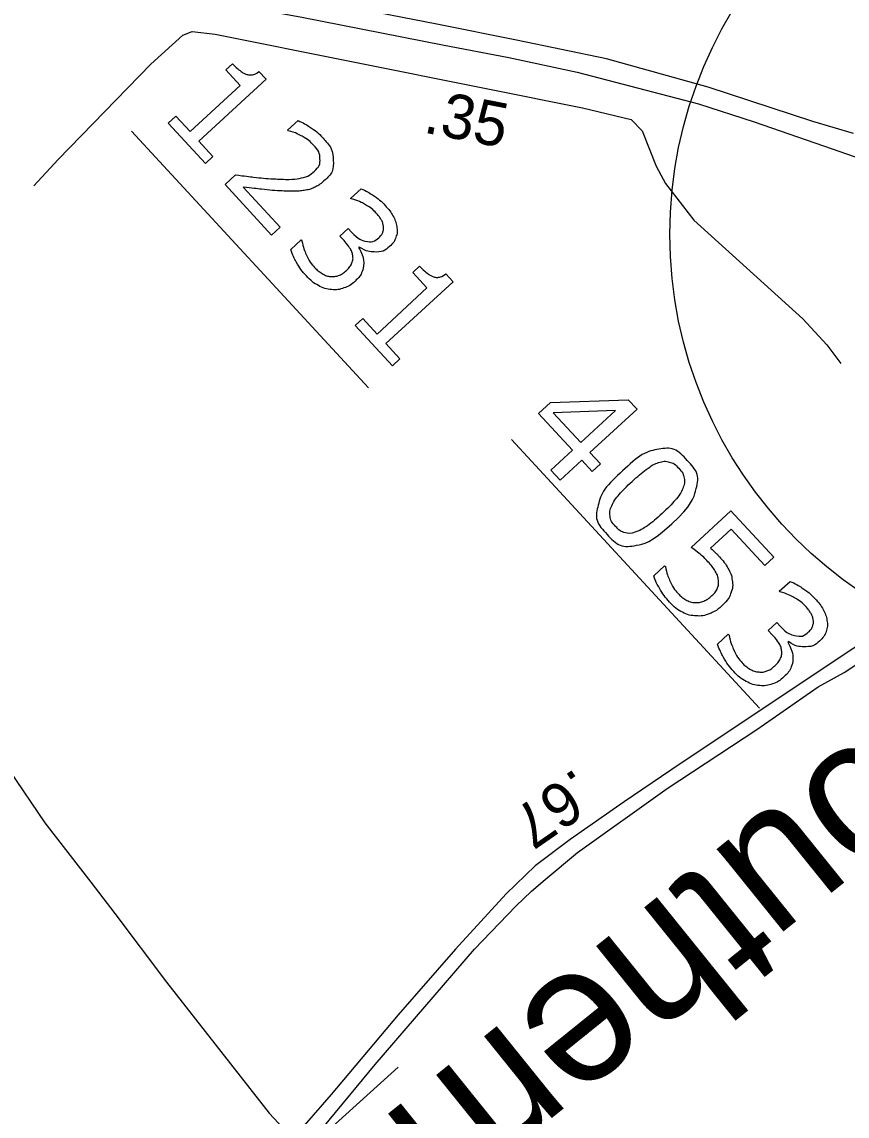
# Model space of a CAD drawing. Extents: x 1695041 to 1706254, y 786537 to 798223.
# Drawn here: x 1703064.1 to 1703171.6, y 796861.2 to 797003.9 of the extents above; entities that cross this region are included whole.
import ezdxf

# ---------------------------------------------------------------- set-up
doc = ezdxf.new("R2010")
doc.units = 0
for name, color, linetype in [('Default', 7, 'Continuous'), ('Old_Level_13', 7, 'Continuous'), ('Old_Level_27', 7, 'Continuous'), ('Old_Level_32', 7, 'Continuous'), ('Old_Level_47', 7, 'Continuous')]:
    doc.layers.add(name, color=color, linetype=linetype)

msp = doc.modelspace()

# ---------------------------------------------------------------- linework, layer by layer
at = {"layer": 'Default'}
for p, q in [((1703078.39, 796989.65), (1703109.28, 796956.18)), ((1703127.89, 796949.43), (1703160.2, 796914.43))]:
    msp.add_line(p, q, dxfattribs=at)
for points in [[(1703088.02, 796985.44), (1703083.17, 796990.7), (1703084.16, 796991.61), (1703086.02, 796989.59), (1703092.53, 796995.6), (1703090.67, 796997.62), (1703091.55, 796998.44)], [(1703095, 796997.43), (1703095.93, 796996.42), (1703087.18, 796988.34), (1703089.01, 796986.36), (1703088.02, 796985.44)], [(1703098.8, 796989.7), (1703098.74, 796989.76), (1703100.11, 796991.02)], [(1703096.65, 796976.09), (1703090.58, 796982.67), (1703091.95, 796983.94)], [(1703092.95, 796982.36), (1703097.78, 796977.13), (1703096.65, 796976.09)], [(1703107, 796980.82), (1703106.93, 796980.88), (1703108.3, 796982.14)], [(1703106.08, 796975.37), (1703105.54, 796975.96), (1703106.62, 796976.95), (1703107.04, 796976.49)], [(1703099.14, 796974.21), (1703100.51, 796975.46), (1703100.6, 796975.36)], [(1703108.09, 796974.54), (1703107.99, 796974.46)], [(1703112.38, 796959.05), (1703107.53, 796964.3), (1703108.52, 796965.22), (1703110.39, 796963.2), (1703116.89, 796969.2), (1703115.03, 796971.22), (1703115.92, 796972.04)], [(1703119.36, 796971.03), (1703120.29, 796970.02), (1703111.54, 796961.95), (1703113.37, 796959.96), (1703112.38, 796959.05)], [(1703138.43, 796945.26), (1703137.05, 796946.75), (1703134.23, 796944.14), (1703133.04, 796945.44), (1703135.86, 796948.04), (1703131.42, 796952.85), (1703132.97, 796954.28), (1703143.11, 796954.64), (1703144.26, 796953.4), (1703138.13, 796947.75), (1703139.51, 796946.26), (1703138.43, 796945.26)], [(1703136.94, 796949.04), (1703141.47, 796953.22), (1703133.35, 796952.93), (1703136.94, 796949.04)], [(1703151.33, 796935.37), (1703156.5, 796940.14), (1703162.07, 796934.11), (1703160.89, 796933.02), (1703156.51, 796937.76), (1703153.85, 796935.3)], [(1703146.44, 796931.66), (1703147.86, 796932.97), (1703147.95, 796932.88)], [(1703162.86, 796929.59), (1703162.8, 796929.66), (1703164.2, 796930.95)], [(1703161.91, 796923.96), (1703161.35, 796924.56), (1703162.47, 796925.59), (1703162.9, 796925.12)], [(1703154.75, 796922.76), (1703156.15, 796924.06), (1703156.25, 796923.95)], [(1703163.98, 796923.1), (1703163.89, 796923.01)], [(1702939.35, 796710.42), (1703049.92, 796810.44), (1703113.12, 796867.61)]]:
    msp.add_lwpolyline(points, dxfattribs=at)
msp.add_circle((1703204.73, 796976.2), 56.19, dxfattribs=at)
for points in [[(1703091.55, 796998.44), (1703091.93, 796998.03), (1703092.43, 796997.62), (1703092.94, 796997.21), (1703093.29, 796997.09), (1703093.73, 796996.94), (1703094.14, 796997), (1703094.55, 796997.06), (1703095, 796997.43)], [(1703100.11, 796991.02), (1703100.76, 796990.77), (1703101.67, 796990.17), (1703102.57, 796989.57), (1703103.24, 796988.85), (1703104.62, 796987.35), (1703104.68, 796985.84), (1703104.75, 796984.33), (1703103.51, 796983.19), (1703102.96, 796982.68), (1703102.35, 796982.38), (1703101.74, 796982.07), (1703101.06, 796981.95), (1703100.42, 796981.83), (1703099.72, 796981.81), (1703099.01, 796981.8), (1703098.08, 796981.85), (1703096.75, 796981.91), (1703095.42, 796982.06), (1703094.1, 796982.22), (1703092.95, 796982.36)], [(1703091.95, 796983.94), (1703093.17, 796983.79), (1703094.4, 796983.64), (1703095.62, 796983.5), (1703096.75, 796983.44), (1703099.12, 796983.3), (1703100.26, 796983.49), (1703101.4, 796983.69), (1703102.23, 796984.45), (1703102.98, 796985.15), (1703102.95, 796986.05), (1703102.91, 796986.94), (1703102.09, 796987.84), (1703101.54, 796988.43), (1703100.69, 796988.93), (1703099.84, 796989.43), (1703098.8, 796989.7)], [(1703108.3, 796982.14), (1703108.95, 796981.89), (1703109.86, 796981.29), (1703110.76, 796980.69), (1703111.43, 796979.97), (1703112.09, 796979.26), (1703112.46, 796978.6), (1703112.83, 796977.93), (1703112.94, 796977.23), (1703113.07, 796976.47), (1703112.84, 796975.82), (1703112.62, 796975.17), (1703112.03, 796974.62), (1703111.22, 796973.88), (1703110.09, 796973.89), (1703108.96, 796973.91), (1703108.09, 796974.54)], [(1703107.04, 796976.49), (1703107.96, 796975.5), (1703108.92, 796975.29), (1703109.88, 796975.09), (1703110.67, 796975.82), (1703111.03, 796976.15), (1703111.15, 796976.54), (1703111.28, 796976.94), (1703111.2, 796977.36), (1703111.11, 796977.8), (1703110.88, 796978.18), (1703110.65, 796978.56), (1703110.28, 796978.96), (1703109.71, 796979.58), (1703108.84, 796980.08), (1703107.97, 796980.57), (1703107, 796980.82)], [(1703100.6, 796975.36), (1703100.74, 796974.47), (1703101.19, 796973.5), (1703101.65, 796972.53), (1703102.29, 796971.83), (1703102.67, 796971.42), (1703103.24, 796971.08), (1703103.8, 796970.74), (1703104.33, 796970.7), (1703104.9, 796970.67), (1703105.38, 796970.84), (1703105.86, 796971.01), (1703106.39, 796971.5), (1703106.92, 796971.99), (1703107.1, 796972.47), (1703107.29, 796972.95), (1703107.22, 796973.43), (1703107.15, 796973.91), (1703106.84, 796974.4), (1703106.53, 796974.88), (1703106.08, 796975.37)], [(1703108.66, 796972.47), (1703108.66, 796971.9), (1703108.43, 796971.3), (1703108.19, 796970.71), (1703107.52, 796970.09), (1703106.85, 796969.47), (1703106.07, 796969.2), (1703105.3, 796968.93), (1703104.48, 796968.99), (1703103.57, 796969.06), (1703102.74, 796969.52), (1703101.91, 796969.98), (1703101.19, 796970.77), (1703100.44, 796971.57), (1703099.91, 796972.53), (1703099.38, 796973.49), (1703099.14, 796974.21)], [(1703107.99, 796974.46), (1703108.23, 796974.09), (1703108.44, 796973.54), (1703108.64, 796972.98), (1703108.66, 796972.47)], [(1703115.92, 796972.04), (1703116.3, 796971.63), (1703116.8, 796971.23), (1703117.3, 796970.82), (1703117.65, 796970.7), (1703118.09, 796970.55), (1703118.5, 796970.61), (1703118.91, 796970.67), (1703119.36, 796971.03)], [(1703148.79, 796938.44), (1703146.08, 796935.95), (1703144.04, 796935.63), (1703142, 796935.3), (1703140.35, 796937.08), (1703138.69, 796938.88), (1703139.2, 796940.9), (1703139.72, 796942.91), (1703142.37, 796945.37), (1703145.05, 796947.84), (1703147.11, 796948.18), (1703149.16, 796948.51), (1703150.81, 796946.73), (1703152.47, 796944.93), (1703151.94, 796942.9), (1703151.41, 796940.87), (1703148.79, 796938.44)], [(1703144.09, 796937.39), (1703144.86, 796937.66), (1703145.67, 796938.26), (1703146.49, 796938.85), (1703147.53, 796939.81), (1703148.55, 796940.76), (1703149.23, 796941.54), (1703149.91, 796942.32), (1703150.21, 796943.05), (1703150.51, 796943.76), (1703150.4, 796944.41), (1703150.29, 796945.06), (1703149.7, 796945.7), (1703149.11, 796946.34), (1703148.47, 796946.51), (1703147.82, 796946.68), (1703147.07, 796946.43), (1703146.35, 796946.2), (1703145.47, 796945.54), (1703144.59, 796944.88), (1703143.64, 796944), (1703142.58, 796943.03), (1703141.95, 796942.3), (1703141.31, 796941.57), (1703140.97, 796940.81), (1703140.65, 796940.11), (1703140.75, 796939.44), (1703140.85, 796938.78), (1703141.47, 796938.11), (1703142.05, 796937.48), (1703142.7, 796937.3), (1703143.35, 796937.13), (1703144.09, 796937.39)], [(1703147.95, 796932.88), (1703148.11, 796932), (1703148.54, 796931.04), (1703148.98, 796930.07), (1703149.64, 796929.35), (1703150.08, 796928.88), (1703150.63, 796928.55), (1703151.18, 796928.23), (1703151.84, 796928.19), (1703152.4, 796928.16), (1703152.95, 796928.38), (1703153.49, 796928.61), (1703154.03, 796929.1), (1703154.55, 796929.58), (1703154.74, 796930.09), (1703154.93, 796930.6), (1703154.86, 796931.11), (1703154.79, 796931.7), (1703154.43, 796932.3), (1703154.07, 796932.9), (1703153.5, 796933.51), (1703152.96, 796934.11), (1703152.37, 796934.58), (1703151.78, 796935.05), (1703151.33, 796935.37)], [(1703153.85, 796935.3), (1703154.14, 796935.04), (1703154.43, 796934.74), (1703154.73, 796934.45), (1703154.93, 796934.23), (1703155.68, 796933.42), (1703156.11, 796932.68), (1703156.54, 796931.93), (1703156.66, 796931.1), (1703156.79, 796930.22), (1703156.48, 796929.38), (1703156.16, 796928.54), (1703155.28, 796927.73)], [(1703155.28, 796927.73), (1703154.58, 796927.08), (1703153.7, 796926.74), (1703152.83, 796926.41), (1703151.98, 796926.45), (1703151.06, 796926.5), (1703150.19, 796926.93), (1703149.32, 796927.37), (1703148.5, 796928.25), (1703147.74, 796929.08), (1703147.21, 796930), (1703146.68, 796930.91), (1703146.44, 796931.66)], [(1703164.2, 796930.95), (1703164.88, 796930.69), (1703165.81, 796930.08), (1703166.75, 796929.46), (1703167.44, 796928.71), (1703168.12, 796927.98), (1703168.5, 796927.29), (1703168.88, 796926.61), (1703169, 796925.88), (1703169.13, 796925.1), (1703168.9, 796924.43), (1703168.67, 796923.75), (1703168.06, 796923.19), (1703167.22, 796922.42), (1703166.06, 796922.43), (1703164.89, 796922.45), (1703163.98, 796923.1)], [(1703162.9, 796925.12), (1703163.85, 796924.09), (1703164.84, 796923.88), (1703165.83, 796923.67), (1703166.66, 796924.43), (1703167.02, 796924.76), (1703167.15, 796925.17), (1703167.28, 796925.58), (1703167.2, 796926.02), (1703167.11, 796926.47), (1703166.87, 796926.86), (1703166.63, 796927.25), (1703166.25, 796927.67), (1703165.66, 796928.31), (1703164.76, 796928.82), (1703163.87, 796929.33), (1703162.86, 796929.59)], [(1703156.25, 796923.95), (1703156.4, 796923.03), (1703156.87, 796922.03), (1703157.33, 796921.02), (1703158, 796920.3), (1703158.39, 796919.87), (1703158.97, 796919.53), (1703159.56, 796919.18), (1703160.11, 796919.14), (1703160.69, 796919.1), (1703161.19, 796919.28), (1703161.69, 796919.46), (1703162.23, 796919.96), (1703162.77, 796920.46), (1703162.97, 796920.96), (1703163.17, 796921.46), (1703163.09, 796921.95), (1703163.02, 796922.45), (1703162.7, 796922.95), (1703162.38, 796923.46), (1703161.91, 796923.96)], [(1703164.57, 796920.96), (1703164.58, 796920.37), (1703164.34, 796919.76), (1703164.09, 796919.15), (1703163.4, 796918.5), (1703162.71, 796917.87), (1703161.9, 796917.59), (1703161.1, 796917.31), (1703160.26, 796917.37), (1703159.32, 796917.44), (1703158.47, 796917.91), (1703157.61, 796918.39), (1703156.86, 796919.2), (1703156.09, 796920.04), (1703155.54, 796921.03), (1703154.99, 796922.02), (1703154.75, 796922.76)], [(1703163.89, 796923.01), (1703164.13, 796922.64), (1703164.35, 796922.07), (1703164.56, 796921.49), (1703164.57, 796920.96)]]:
    msp.add_open_spline(points, degree=3, dxfattribs=at)
at = {"layer": 'Old_Level_13'}
msp.add_lwpolyline([(1703102.51, 796858.71), (1703110.13, 796867.99), (1703123.07, 796883.01), (1703128.45, 796888.6), (1703130.5, 796890.56), (1703132.31, 796892.08), (1703136.49, 796895.6), (1703148.18, 796903.94), (1703159.85, 796911.65), (1703167.86, 796917.19), (1703171.23, 796919.07), (1703180.72, 796925.38)], dxfattribs=at)
at = {"layer": 'Old_Level_27'}
for points in [[(1703172.45, 796989.35), (1703167.18, 796990.92), (1703153.51, 796995.4), (1703140.28, 796999.08), (1703128.56, 797001.52), (1703118.19, 797003.6), (1703098.49, 797007.45), (1703084.8, 797010.03), (1703063.68, 797014.04), (1703056.42, 797015.68), (1703042.53, 797018.06), (1703034.36, 797019.5)], [(1703033.89, 797016.84), (1703041.88, 797015.36), (1703063.82, 797011.42), (1703087.73, 797006.89), (1703100.58, 797004.49), (1703118.9, 797000.91), (1703127.55, 796999.23), (1703136.45, 796997.33), (1703152.27, 796993.21), (1703159.52, 796990.84), (1703169.7, 796987.34), (1703186.53, 796981.49)]]:
    msp.add_lwpolyline(points, dxfattribs=at)
at = {"layer": 'Old_Level_32'}
for points in [[(1703200.34, 796950.4), (1703199.72, 796948.4), (1703198.35, 796945.06), (1703196.68, 796941.88), (1703194.52, 796939.14), (1703191.06, 796935.5), (1703186.5, 796931.59), (1703182.53, 796928.81), (1703172.52, 796922.24), (1703149.9, 796907.16), (1703142.6, 796902.2), (1703135.53, 796897.31), (1703131, 796893.87), (1703127.2, 796890.2), (1703120.59, 796883.01), (1703113.14, 796874.43), (1703104.41, 796864.08), (1703099.4, 796858.32)], [(1703062.44, 796906.34), (1703067.1, 796899.48), (1703073.08, 796891.75), (1703076.21, 796887.64), (1703082.95, 796878.71), (1703096.34, 796861.63), (1703099.4, 796858.32)]]:
    msp.add_lwpolyline(points, dxfattribs=at)
at = {"layer": 'Old_Level_47'}
msp.add_lwpolyline([(1703065.65, 796982.53), (1703068.84, 796985.93), (1703080.92, 796998.36), (1703085.08, 797002.17), (1703086.29, 797002.63), (1703089.3, 797002.29), (1703124.83, 796995.17), (1703137.14, 796992.67), (1703143.48, 796991.15), (1703144.94, 796989.68), (1703146.74, 796985.07), (1703147.95, 796982.82), (1703151.65, 796978.02), (1703165.85, 796965.17), (1703168.98, 796961.77), (1703170.81, 796959.36)], dxfattribs=at)

# ---------------------------------------------------------------- texts
at = {"layer": 'Default'}
for s, height, rotation, p in [('.35', 5.775, 348.9589, (1703116.28, 796989.5)), ('Southern', 18.015, 218.8645, (1703186.73, 796921.93)), ('.67', 5.775, 214.724, (1703136.3, 796906.7))]:
    msp.add_text(s, height=height, rotation=rotation, dxfattribs=at).set_placement(p)

doc.saveas('drawing.dxf')
